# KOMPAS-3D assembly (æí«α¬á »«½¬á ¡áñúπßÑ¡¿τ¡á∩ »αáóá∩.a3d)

Referenced files in D:\АСКОН работа\Конкурс HOME\06_Сюваев_Сборная модель танка Т90\ДЕТАЛИ\КОРПУС\МЕТАЛЛ\КОРПУС ШТАМПОВКА\: полка надгусеничная правая.m3d, брызговик правый.m3d
Referenced files in D:\АСКОН работа\Конкурс HOME\06_Сюваев_Сборная модель танка Т90\ДЕТАЛИ\КОРПУС\МЕТАЛЛ\КОРПУС ШТАМПОВКА\БАКИ\: Сборка бак правый 5.a3d, Сборка бак правый 1.a3d, Сборка бак правый 2.a3d, Сборка бак правый 3.a3d, Сборка бак правый 4.a3d
Referenced files in D:\АСКОН работа\Конкурс HOME\06_Сюваев_Сборная модель танка Т90\СБОРКИ\СБОРКА КОРПУСА ШТАМПОВКА\: Сборка экран правый.a3d
Referenced files in D:\АСКОН работа\Конкурс HOME\06_Сюваев_Сборная модель танка Т90\ДЕТАЛИ\ОБЩИЕ ДЕТАЛИ\: брызговик задний правый.m3d, поворот задн прав.m3d, ДЗ.m3d
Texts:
  Сборка полка надгусеничная правая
